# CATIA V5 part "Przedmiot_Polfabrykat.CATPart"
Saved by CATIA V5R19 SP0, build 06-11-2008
Bounding box of the stored display mesh (mm): x -74.453 to 5.547, y -76.893 to 63.107, z 0 to 30
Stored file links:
  G:\Catia\CD\Narzedzia\Excel\Przedmiot_Polfabrykat.CATPart
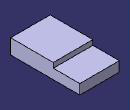
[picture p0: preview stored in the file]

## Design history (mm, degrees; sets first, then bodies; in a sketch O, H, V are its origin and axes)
Body1 "Przedmiot" (main body)
  Sketch1 on xy-plane, origin (0, 0, 0), H (1, 0, 0), V (0, 1, 0)
    line L1 (-74.4526, 63.107) -> (5.5474, 63.107)
    line L2 (5.5474, 63.107) -> (5.5474, -76.893)
    line L3 (5.5474, -76.893) -> (-74.4526, -76.893)
    line L4 (-74.4526, -76.893) -> (-74.4526, 63.107)
    length L2 = 140
    length L1 = 80
    horizontal: L1 H, L3 H
    vertical: L2 V, L4 V
  Pad1: profile Sketch1, direction (0, 0, 1), length 30
  Sketch2 on end face of Pad1, origin (0, 0, 30), H (1, 0, 0), V (0, 1, 0)
    line L1 (-94.2681, 69.1692) -> (13.2449, 69.1692)
    line L2 (13.2449, 69.1692) -> (13.2449, 9.4398)
    line L3 (13.2449, 9.4398) -> (-94.2681, 9.4398)
    line L4 (-94.2681, 9.4398) -> (-94.2681, 69.1692)
    horizontal: L1 H, L3 H
    vertical: L2 V, L4 V
  Pocket1: profile Sketch2, direction (0, 0, -1), length 10
Body2 "Polfabrykat"
  Sketch3 on xy-plane, origin (0, 0, 0), H (1, 0, 0), V (0, 1, 0)
    construction line L1 through (0, 0) direction (1, 0)
    line L2 (-74.4526, 63.107) -> (5.5474, 63.107)
    line L3 (5.5474, -76.893) -> (-74.4526, -76.893)
    construction line L4 through (0, 0) direction (0, 1)
    line L5 (5.5474, 63.107) -> (5.5474, -76.893)
    line L6 (-74.4526, -76.893) -> (-74.4526, 63.107)
    point P1 (0, 0)
    length L5 = 140
    length L2 = 80
    horizontal: L2 L1, L3 L1
    vertical: L5 L4, L6 L4
  Pad2: profile Sketch3, direction (0, 0, 1), length 30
